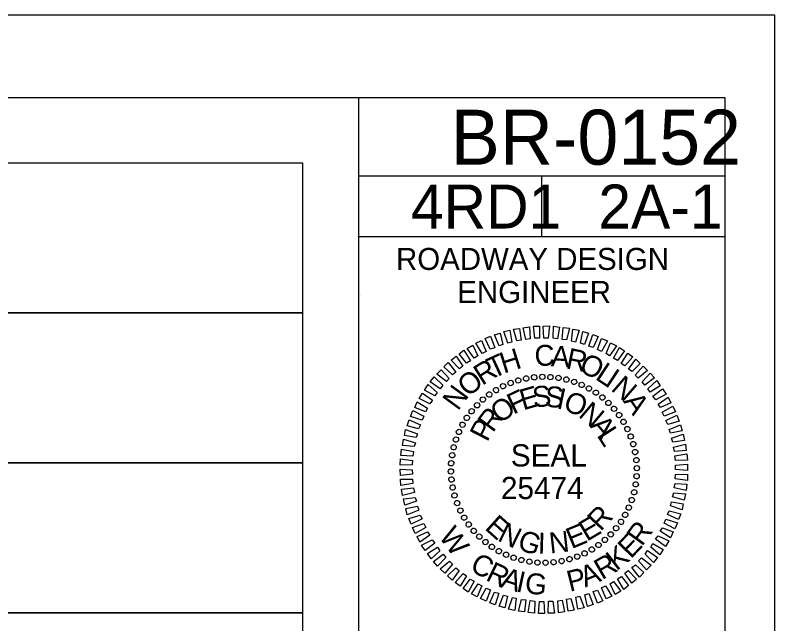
# Model space of a CAD drawing. Extents: x 1553884 to 1554215, y 810431 to 810779.
# Drawn here: x 1554125.27 to 1554156.35, y 810754.53 to 810779.43 of the extents above; entities that cross this region are included whole.
import ezdxf

# ---------------------------------------------------------------- set-up
doc = ezdxf.new("R2010")
doc.units = 0
for name, color, linetype in [('Exist Structure Minor Drop Inlet Top Elevation', 7, 'Continuous'), ('Old_Level_2', 7, 'Continuous'), ('Prop Dimension', 7, 'Continuous'), ('Prop Lane Arrow CELL', 7, 'Continuous'), ('Typical Arrow Superelevation CELL', 7, 'Continuous')]:
    doc.layers.add(name, color=color, linetype=linetype)

msp = doc.modelspace()

# ---------------------------------------------------------------- linework, layer by layer
at = {"layer": 'Exist Structure Minor Drop Inlet Top Elevation'}
for p, q in [((1554139.415, 810767.944), (1554139.415, 810767.944)), ((1554145.537, 810764.389), (1554145.537, 810764.389)), ((1554145.853, 810764.493), (1554145.853, 810764.493)), ((1554146.178, 810764.567), (1554146.178, 810764.567)), ((1554146.503, 810764.618), (1554146.503, 810764.618)), ((1554146.837, 810764.639), (1554146.837, 810764.639)), ((1554147.171, 810764.63), (1554147.171, 810764.63)), ((1554147.497, 810764.59), (1554147.497, 810764.59)), ((1554147.824, 810764.527), (1554147.824, 810764.527)), ((1554148.144, 810764.435), (1554148.144, 810764.435)), ((1554144.943, 810764.098), (1554144.943, 810764.098)), ((1554145.236, 810764.255), (1554145.236, 810764.255)), ((1554148.45, 810764.311), (1554148.45, 810764.311)), ((1554148.748, 810764.165), (1554148.748, 810764.165)), ((1554144.665, 810763.911), (1554144.665, 810763.911)), ((1554149.032, 810763.987), (1554149.032, 810763.987)), ((1554149.301, 810763.795), (1554149.301, 810763.795)), ((1554144.165, 810763.478), (1554144.165, 810763.478)), ((1554144.403, 810763.71), (1554144.403, 810763.71)), ((1554149.547, 810763.572), (1554149.547, 810763.572)), ((1554143.942, 810763.231), (1554143.942, 810763.231)), ((1554149.779, 810763.333), (1554149.779, 810763.333)), ((1554143.749, 810762.962), (1554143.749, 810762.962)), ((1554149.981, 810763.071), (1554149.981, 810763.071)), ((1554143.572, 810762.679), (1554143.572, 810762.679)), ((1554150.168, 810762.794), (1554150.168, 810762.794)), ((1554143.426, 810762.38), (1554143.426, 810762.38)), ((1554150.324, 810762.501), (1554150.324, 810762.501)), ((1554150.459, 810762.2), (1554150.459, 810762.2)), ((1554143.302, 810762.075), (1554143.302, 810762.075)), ((1554143.209, 810761.755), (1554143.209, 810761.755)), ((1554150.563, 810761.883), (1554150.563, 810761.883)), ((1554143.146, 810761.428), (1554143.146, 810761.428)), ((1554150.637, 810761.558), (1554150.637, 810761.558)), ((1554143.107, 810761.101), (1554143.107, 810761.101)), ((1554150.688, 810761.233), (1554150.688, 810761.233)), ((1554143.097, 810760.767), (1554143.097, 810760.767)), ((1554146.903, 810760.833), (1554146.903, 810760.833)), ((1554150.709, 810760.9), (1554150.709, 810760.9)), ((1554143.118, 810760.434), (1554143.118, 810760.434)), ((1554150.699, 810760.566), (1554150.699, 810760.566)), ((1554143.17, 810760.108), (1554143.17, 810760.108)), ((1554150.66, 810760.239), (1554150.66, 810760.239)), ((1554143.243, 810759.784), (1554143.243, 810759.784)), ((1554150.597, 810759.912), (1554150.597, 810759.912)), ((1554143.348, 810759.467), (1554143.348, 810759.467)), ((1554150.504, 810759.592), (1554150.504, 810759.592)), ((1554143.482, 810759.166), (1554143.482, 810759.166)), ((1554150.38, 810759.286), (1554150.38, 810759.286)), ((1554143.639, 810758.873), (1554143.639, 810758.873)), ((1554150.234, 810758.988), (1554150.234, 810758.988)), ((1554143.825, 810758.596), (1554143.825, 810758.596)), ((1554150.057, 810758.705), (1554150.057, 810758.705)), ((1554144.027, 810758.334), (1554144.027, 810758.334)), ((1554149.641, 810758.189), (1554149.641, 810758.189)), ((1554149.865, 810758.436), (1554149.865, 810758.436)), ((1554144.259, 810758.095), (1554144.259, 810758.095)), ((1554144.505, 810757.872), (1554144.505, 810757.872)), ((1554149.403, 810757.957), (1554149.403, 810757.957)), ((1554144.774, 810757.68), (1554144.774, 810757.68)), ((1554148.864, 810757.569), (1554148.864, 810757.569)), ((1554149.141, 810757.756), (1554149.141, 810757.756)), ((1554145.058, 810757.502), (1554145.058, 810757.502)), ((1554145.356, 810757.356), (1554145.356, 810757.356)), ((1554145.662, 810757.232), (1554145.662, 810757.232)), ((1554148.269, 810757.278), (1554148.269, 810757.278)), ((1554148.571, 810757.412), (1554148.571, 810757.412)), ((1554145.982, 810757.139), (1554145.982, 810757.139)), ((1554146.309, 810757.077), (1554146.309, 810757.077)), ((1554146.636, 810757.037), (1554146.636, 810757.037)), ((1554146.969, 810757.028), (1554146.969, 810757.028)), ((1554147.303, 810757.049), (1554147.303, 810757.049)), ((1554147.628, 810757.1), (1554147.628, 810757.1)), ((1554147.953, 810757.174), (1554147.953, 810757.174))]:
    msp.add_line(p, q, dxfattribs=at)
for points in [[(1554145.795, 810766.107), (1554145.658, 810766.583), (1554145.907, 810766.617), (1554145.976, 810766.133)], [(1554146.158, 810766.167), (1554146.058, 810766.643), (1554146.308, 810766.685), (1554146.339, 810766.193)], [(1554146.536, 810766.211), (1554146.475, 810766.703), (1554146.725, 810766.707), (1554146.718, 810766.214)], [(1554146.9, 810766.218), (1554146.876, 810766.71), (1554147.126, 810766.714), (1554147.082, 810766.221)], [(1554147.279, 810766.209), (1554147.293, 810766.702), (1554147.544, 810766.669), (1554147.462, 810766.189)], [(1554147.644, 810766.162), (1554147.696, 810766.649), (1554147.947, 810766.623), (1554147.827, 810766.143)], [(1554148.032, 810766.093), (1554148.092, 810766.587), (1554148.351, 810766.539), (1554148.192, 810766.058)], [(1554144.709, 810765.762), (1554144.496, 810766.198), (1554144.715, 810766.293), (1554144.89, 810765.819)], [(1554145.07, 810765.898), (1554144.881, 810766.349), (1554145.114, 810766.422), (1554145.229, 810765.953)], [(1554145.432, 810766.01), (1554145.257, 810766.485), (1554145.514, 810766.542), (1554145.591, 810766.051)], [(1554148.398, 810766.009), (1554148.496, 810766.481), (1554148.732, 810766.416), (1554148.558, 810765.958)], [(1554148.741, 810765.886), (1554148.899, 810766.366), (1554149.121, 810766.279), (1554148.924, 810765.836)], [(1554144.055, 810765.402), (1554143.76, 810765.799), (1554143.993, 810765.932), (1554144.198, 810765.496)], [(1554144.378, 810765.59), (1554144.121, 810766.01), (1554144.354, 810766.12), (1554144.544, 810765.668)], [(1554149.092, 810765.748), (1554149.266, 810766.206), (1554149.503, 810766.104), (1554149.26, 810765.675)], [(1554149.444, 810765.587), (1554149.633, 810766.03), (1554149.871, 810765.905), (1554149.59, 810765.499)], [(1554143.733, 810765.199), (1554143.438, 810765.573), (1554143.633, 810765.728), (1554143.898, 810765.293)], [(1554149.751, 810765.395), (1554150.001, 810765.839), (1554150.201, 810765.691), (1554149.919, 810765.307)], [(1554143.449, 810764.959), (1554143.109, 810765.317), (1554143.311, 810765.48), (1554143.591, 810765.068)], [(1554150.065, 810765.181), (1554150.331, 810765.603), (1554150.538, 810765.447), (1554150.211, 810765.077)], [(1554150.365, 810764.951), (1554150.661, 810765.358), (1554150.846, 810765.179), (1554150.511, 810764.847)], [(1554143.157, 810764.719), (1554142.81, 810765.039), (1554142.989, 810765.224), (1554143.299, 810764.828)], [(1554150.643, 810764.698), (1554150.962, 810765.068), (1554151.147, 810764.889), (1554150.766, 810764.579)], [(1554142.912, 810764.442), (1554142.52, 810764.738), (1554142.699, 810764.923), (1554143.031, 810764.565)], [(1554150.92, 810764.43), (1554151.255, 810764.784), (1554151.425, 810764.59), (1554151.029, 810764.288)], [(1554142.659, 810764.142), (1554142.252, 810764.43), (1554142.416, 810764.63), (1554142.763, 810764.287)], [(1554151.16, 810764.146), (1554151.518, 810764.478), (1554151.666, 810764.261), (1554151.254, 810764.003)], [(1554142.444, 810763.85), (1554142.023, 810764.093), (1554142.163, 810764.315), (1554142.533, 810763.995)], [(1554151.363, 810763.839), (1554151.759, 810764.141), (1554151.907, 810763.924), (1554151.479, 810763.697)], [(1554142.23, 810763.535), (1554141.794, 810763.747), (1554141.934, 810763.97), (1554142.341, 810763.681)], [(1554151.573, 810763.516), (1554151.985, 810763.796), (1554152.095, 810763.563), (1554151.667, 810763.374)], [(1554142.054, 810763.206), (1554141.618, 810763.38), (1554141.72, 810763.617), (1554142.142, 810763.351)], [(1554141.916, 810762.855), (1554141.443, 810763.013), (1554141.545, 810763.25), (1554141.989, 810763.023)], [(1554151.738, 810763.193), (1554152.174, 810763.436), (1554152.284, 810763.202), (1554151.817, 810763.027)], [(1554141.778, 810762.511), (1554141.305, 810762.632), (1554141.392, 810762.868), (1554141.851, 810762.671)], [(1554151.888, 810762.847), (1554152.339, 810763.059), (1554152.435, 810762.826), (1554151.967, 810762.689)], [(1554152.023, 810762.485), (1554152.498, 810762.675), (1554152.555, 810762.426), (1554152.079, 810762.327)], [(1554141.678, 810762.145), (1554141.199, 810762.228), (1554141.247, 810762.479), (1554141.728, 810762.305)], [(1554152.121, 810762.123), (1554152.596, 810762.283), (1554152.653, 810762.026), (1554152.176, 810761.964)], [(1554141.593, 810761.78), (1554141.115, 810761.824), (1554141.163, 810762.083), (1554141.644, 810761.94)], [(1554141.539, 810761.392), (1554141.054, 810761.421), (1554141.079, 810761.68), (1554141.574, 810761.575)], [(1554152.203, 810761.76), (1554152.694, 810761.882), (1554152.728, 810761.625), (1554152.244, 810761.579)], [(1554141.515, 810761.027), (1554141.023, 810761.019), (1554141.033, 810761.277), (1554141.527, 810761.21)], [(1554152.262, 810761.397), (1554152.754, 810761.482), (1554152.773, 810761.224), (1554152.281, 810761.216)], [(1554152.284, 810761.018), (1554152.776, 810761.065), (1554152.781, 810760.807), (1554152.287, 810760.836)], [(1554141.522, 810760.648), (1554141.03, 810760.602), (1554141.025, 810760.86), (1554141.519, 810760.831)], [(1554152.291, 810760.639), (1554152.783, 810760.648), (1554152.773, 810760.39), (1554152.279, 810760.457)], [(1554141.544, 810760.27), (1554141.052, 810760.185), (1554141.033, 810760.443), (1554141.525, 810760.451)], [(1554141.603, 810759.907), (1554141.112, 810759.784), (1554141.078, 810760.042), (1554141.562, 810760.088)], [(1554152.267, 810760.275), (1554152.753, 810760.245), (1554152.727, 810759.987), (1554152.232, 810760.092)], [(1554152.213, 810759.887), (1554152.691, 810759.842), (1554152.643, 810759.584), (1554152.163, 810759.727)], [(1554141.685, 810759.544), (1554141.21, 810759.384), (1554141.153, 810759.641), (1554141.63, 810759.702)], [(1554152.128, 810759.522), (1554152.607, 810759.439), (1554152.559, 810759.188), (1554152.078, 810759.362)], [(1554141.783, 810759.182), (1554141.308, 810758.992), (1554141.251, 810759.241), (1554141.727, 810759.34)], [(1554152.028, 810759.156), (1554152.501, 810759.035), (1554152.414, 810758.799), (1554151.955, 810758.995)], [(1554141.918, 810758.82), (1554141.467, 810758.608), (1554141.372, 810758.841), (1554141.839, 810758.978)], [(1554151.89, 810758.812), (1554152.363, 810758.654), (1554152.261, 810758.417), (1554151.817, 810758.644)], [(1554142.068, 810758.474), (1554141.632, 810758.231), (1554141.522, 810758.465), (1554141.989, 810758.639)], [(1554142.233, 810758.151), (1554141.821, 810757.871), (1554141.711, 810758.104), (1554142.139, 810758.293)], [(1554151.752, 810758.461), (1554152.188, 810758.287), (1554152.086, 810758.05), (1554151.664, 810758.316)], [(1554142.443, 810757.828), (1554142.047, 810757.526), (1554141.899, 810757.743), (1554142.327, 810757.97)], [(1554151.576, 810758.132), (1554152.012, 810757.92), (1554151.872, 810757.697), (1554151.465, 810757.986)], [(1554142.646, 810757.521), (1554142.288, 810757.189), (1554142.14, 810757.406), (1554142.552, 810757.664)], [(1554151.362, 810757.817), (1554151.783, 810757.574), (1554151.643, 810757.352), (1554151.273, 810757.672)], [(1554142.886, 810757.237), (1554142.551, 810756.882), (1554142.38, 810757.076), (1554142.777, 810757.379)], [(1554150.894, 810757.225), (1554151.286, 810756.929), (1554151.107, 810756.744), (1554150.775, 810757.102)], [(1554151.147, 810757.525), (1554151.554, 810757.237), (1554151.39, 810757.037), (1554151.043, 810757.379)], [(1554143.164, 810756.969), (1554142.844, 810756.599), (1554142.659, 810756.778), (1554143.04, 810757.088)], [(1554150.649, 810756.948), (1554150.996, 810756.628), (1554150.817, 810756.443), (1554150.507, 810756.839)], [(1554143.441, 810756.716), (1554143.145, 810756.309), (1554142.96, 810756.488), (1554143.295, 810756.819)], [(1554150.357, 810756.708), (1554150.697, 810756.35), (1554150.495, 810756.187), (1554150.215, 810756.599)], [(1554143.741, 810756.486), (1554143.475, 810756.064), (1554143.268, 810756.22), (1554143.595, 810756.59)], [(1554144.056, 810756.272), (1554143.805, 810755.827), (1554143.606, 810755.976), (1554143.887, 810756.36)], [(1554150.073, 810756.468), (1554150.368, 810756.094), (1554150.173, 810755.939), (1554149.908, 810756.374)], [(1554144.362, 810756.08), (1554144.173, 810755.637), (1554143.935, 810755.761), (1554144.217, 810756.168)], [(1554144.714, 810755.919), (1554144.54, 810755.461), (1554144.303, 810755.563), (1554144.546, 810755.992)], [(1554149.428, 810756.077), (1554149.685, 810755.657), (1554149.452, 810755.547), (1554149.262, 810755.999)], [(1554149.751, 810756.265), (1554150.046, 810755.868), (1554149.813, 810755.735), (1554149.608, 810756.171)], [(1554145.065, 810755.781), (1554144.907, 810755.301), (1554144.685, 810755.388), (1554144.882, 810755.831)], [(1554145.408, 810755.658), (1554145.311, 810755.186), (1554145.074, 810755.25), (1554145.248, 810755.708)], [(1554148.736, 810755.769), (1554148.925, 810755.318), (1554148.692, 810755.245), (1554148.577, 810755.713)], [(1554149.097, 810755.905), (1554149.31, 810755.469), (1554149.091, 810755.374), (1554148.916, 810755.848)], [(1554145.774, 810755.574), (1554145.714, 810755.08), (1554145.456, 810755.128), (1554145.614, 810755.609)], [(1554146.162, 810755.505), (1554146.11, 810755.018), (1554145.859, 810755.044), (1554145.98, 810755.524)], [(1554146.527, 810755.458), (1554146.513, 810754.965), (1554146.262, 810754.998), (1554146.344, 810755.477)], [(1554146.906, 810755.449), (1554146.93, 810754.957), (1554146.68, 810754.952), (1554146.724, 810755.446)], [(1554147.27, 810755.456), (1554147.331, 810754.964), (1554147.081, 810754.959), (1554147.088, 810755.452)], [(1554147.648, 810755.5), (1554147.748, 810755.024), (1554147.498, 810754.982), (1554147.467, 810755.474)], [(1554148.011, 810755.559), (1554148.148, 810755.084), (1554147.899, 810755.05), (1554147.83, 810755.534)], [(1554148.374, 810755.657), (1554148.549, 810755.182), (1554148.292, 810755.125), (1554148.215, 810755.616)]]:
    msp.add_lwpolyline(points, close=True, dxfattribs=at)
for centre, major_axis in [((1554146.177, 810764.564), (-0.021, 0.107)), ((1554146.505, 810764.613), (-0.011, 0.109)), ((1554146.836, 810764.633), (-0.002, 0.109)), ((1554147.168, 810764.624), (0.008, 0.109)), ((1554147.497, 810764.587), (0.017, 0.108)), ((1554145.235, 810764.249), (-0.0479, 0.0981)), ((1554145.54, 810764.381), (-0.039, 0.102)), ((1554145.854, 810764.486), (-0.03, 0.105)), ((1554147.823, 810764.521), (0.026, 0.106)), ((1554148.141, 810764.427), (0.036, 0.103)), ((1554148.449, 810764.305), (0.0444, 0.0997)), ((1554144.944, 810764.091), (-0.0562, 0.0936)), ((1554148.746, 810764.157), (0.0529, 0.0955)), ((1554149.029, 810763.984), (0.0611, 0.0905)), ((1554144.407, 810763.701), (-0.0716, 0.0824)), ((1554144.667, 810763.907), (-0.0642, 0.0883)), ((1554149.296, 810763.786), (0.0687, 0.0849)), ((1554144.167, 810763.472), (-0.0785, 0.0758)), ((1554149.544, 810763.566), (0.0758, 0.0785)), ((1554149.773, 810763.326), (0.0824, 0.0716)), ((1554143.947, 810763.224), (-0.0849, 0.0687)), ((1554149.979, 810763.066), (0.0883, 0.0642)), ((1554143.749, 810762.957), (-0.0905, 0.0611)), ((1554150.163, 810762.789), (0.0936, 0.0562)), ((1554143.576, 810762.674), (-0.0955, 0.0529)), ((1554150.321, 810762.498), (0.0981, 0.0479)), ((1554143.428, 810762.377), (-0.0997, 0.0444)), ((1554150.453, 810762.193), (0.102, 0.039)), ((1554143.306, 810762.069), (-0.103, 0.036)), ((1554150.558, 810761.879), (0.105, 0.03)), ((1554143.212, 810761.751), (-0.106, 0.026)), ((1554150.636, 810761.556), (0.107, 0.021)), ((1554143.146, 810761.425), (-0.108, 0.017)), ((1554150.685, 810761.228), (0.109, 0.011)), ((1554143.108, 810761.096), (-0.109, 0.008)), ((1554150.705, 810760.897), (0.109, 0.002)), ((1554143.1, 810760.764), (-0.109, -0.002)), ((1554150.697, 810760.565), (0.109, -0.008)), ((1554143.12, 810760.433), (-0.109, -0.011)), ((1554150.659, 810760.236), (0.108, -0.017)), ((1554143.169, 810760.105), (-0.107, -0.021)), ((1554150.593, 810759.91), (0.106, -0.026)), ((1554143.247, 810759.782), (-0.105, -0.03)), ((1554150.499, 810759.592), (0.103, -0.036)), ((1554143.352, 810759.467), (-0.102, -0.039)), ((1554150.377, 810759.284), (0.0997, -0.0444)), ((1554143.484, 810759.163), (-0.0981, -0.0479)), ((1554150.229, 810758.987), (0.0955, -0.0529)), ((1554143.642, 810758.872), (-0.0936, -0.0562)), ((1554150.056, 810758.704), (0.0905, -0.0611)), ((1554143.826, 810758.595), (-0.0883, -0.0642)), ((1554149.858, 810758.437), (0.0849, -0.0687)), ((1554144.032, 810758.335), (-0.0824, -0.0716)), ((1554144.261, 810758.095), (-0.0758, -0.0785)), ((1554149.638, 810758.188), (0.0785, -0.0758)), ((1554144.509, 810757.875), (-0.0687, -0.0849)), ((1554149.138, 810757.754), (0.0642, -0.0883)), ((1554149.398, 810757.96), (0.0716, -0.0824)), ((1554144.776, 810757.677), (-0.0611, -0.0905)), ((1554145.059, 810757.504), (-0.0529, -0.0955)), ((1554148.57, 810757.412), (0.0479, -0.0981)), ((1554148.861, 810757.57), (0.0562, -0.0936)), ((1554145.356, 810757.356), (-0.0444, -0.0997)), ((1554145.664, 810757.234), (-0.036, -0.103)), ((1554145.982, 810757.14), (-0.026, -0.106)), ((1554147.951, 810757.175), (0.03, -0.105)), ((1554148.265, 810757.28), (0.039, -0.102)), ((1554146.308, 810757.074), (-0.017, -0.108)), ((1554146.637, 810757.036), (-0.008, -0.109)), ((1554146.969, 810757.028), (0.002, -0.109)), ((1554147.3, 810757.048), (0.011, -0.109)), ((1554147.628, 810757.097), (0.021, -0.107))]:
    msp.add_ellipse(centre, major_axis=major_axis, ratio=0.999708, dxfattribs=at)
at = {"layer": 'Old_Level_2'}
for p, q in [((1554154.325, 810776.052), (1553906.825, 810776.052)), ((1554139.321, 810617.805), (1554139.325, 810776.052)), ((1554154.321, 810617.805), (1554154.325, 810776.052)), ((1554154.325, 810772.839), (1554139.325, 810772.839)), ((1554146.825, 810770.364), (1554146.825, 810772.839)), ((1554154.325, 810770.364), (1554139.325, 810770.364))]:
    msp.add_line(p, q, dxfattribs=at)
msp.add_circle((1554139.325, 810770.364), 0.009, dxfattribs=at)
at = {"layer": 'Prop Dimension'}
msp.add_lwpolyline([(1554077.027, 810773.388), (1554137.029, 810773.388), (1554137.029, 810767.252), (1554077.027, 810767.252)], close=True, dxfattribs=at)
for points in [[(1554083.164, 810761.114), (1554077.027, 810761.114), (1554077.027, 810767.252), (1554137.027, 810767.252), (1554137.027, 810761.114), (1554083.164, 810761.114), (1554083.164, 810767.252)], [(1554083.164, 810754.977), (1554077.027, 810754.977), (1554077.027, 810761.114), (1554137.027, 810761.114), (1554137.027, 810754.977), (1554083.164, 810754.977), (1554083.164, 810761.114)], [(1554083.164, 810748.839), (1554077.027, 810748.839), (1554077.027, 810754.977), (1554137.027, 810754.977), (1554137.027, 810748.839), (1554083.164, 810748.839), (1554083.164, 810754.977)]]:
    msp.add_lwpolyline(points, dxfattribs=at)
at = {"layer": 'Prop Lane Arrow CELL'}
for p, q in [((1554156.35, 810779.427), (1553901.353, 810779.427)), ((1554156.35, 810614.43), (1554156.35, 810779.427))]:
    msp.add_line(p, q, dxfattribs=at)

# ---------------------------------------------------------------- texts
at = {"layer": 'Exist Structure Minor Drop Inlet Top Elevation'}
for s, height, rotation, p in [('C', 0.855, 2.9171, (1554146.539, 810765.064)), ('H', 0.855, 17.4535, (1554145.257, 810764.764)), ('A', 0.855, 355.649, (1554147.177, 810765.069)), ('R', 0.855, 348.3808, (1554147.77, 810764.988)), ('T', 0.855, 24.7216, (1554144.817, 810764.545)), ('O', 0.855, 333.8445, (1554148.29, 810764.88)), ('R', 0.855, 31.9898, (1554144.375, 810764.258)), ('L', 0.855, 326.5763, (1554148.962, 810764.559)), ('O', 0.855, 39.2579, (1554143.802, 810763.78)), ('I', 0.855, 326.5763, (1554149.348, 810764.304)), ('N', 0.855, 319.3082, (1554149.609, 810764.104)), ('N', 0.855, 53.7943, (1554143.385, 810763.212)), ('F', 0.855, 25.3292, (1554145.653, 810763.08)), ('E', 0.855, 15.9853, (1554146.053, 810763.258)), ('S', 0.855, 6.6414, (1554146.482, 810763.367)), ('S', 0.855, 357.2975, (1554146.935, 810763.4)), ('I', 0.855, 347.9535, (1554147.387, 810763.353)), ('O', 0.855, 338.6096, (1554147.647, 810763.297)), ('A', 0.855, 304.7718, (1554150.128, 810763.63)), ('O', 0.855, 34.6731, (1554145.089, 810762.697)), ('N', 0.855, 319.9218, (1554148.277, 810763.029)), ('R', 0.855, 53.361, (1554144.811, 810762.319)), ('P', 0.855, 62.7049, (1554144.587, 810761.938)), ('A', 0.855, 310.5779, (1554148.757, 810762.611)), ('L', 0.855, 302.7465, (1554149.046, 810762.244)), ('SEAL', 0.9096, 0, (1554145.549, 810760.965)), ('25474', 0.9099, 0, (1554145.144, 810759.631)), ('R', 0.855, 46.7271, (1554149.224, 810758.285)), ('E', 0.855, 317.8985, (1554144.446, 810758.422)), ('E', 0.855, 30.5764, (1554148.659, 810757.879)), ('W', 0.855, 305.9992, (1554142.575, 810758.105)), ('N', 0.855, 334.0491, (1554144.967, 810757.954)), ('E', 0.855, 22.5011, (1554148.031, 810757.581)), ('R', 0.855, 54, (1554150.913, 810757.667)), ('G', 0.855, 342.1244, (1554145.776, 810757.586)), ('I', 0.855, 358.2751, (1554146.644, 810757.403)), ('N', 0.855, 6.3504, (1554147.162, 810757.404)), ('E', 0.855, 46, (1554150.456, 810757.163)), ('.', 0.855, 310.4999, (1554142.971, 810757.576)), ('K', 0.855, 38, (1554149.869, 810756.672)), ('C', 0.855, 334, (1554143.836, 810756.705)), ('R', 0.855, 30, (1554149.278, 810756.31)), ('R', 0.855, 334, (1554144.481, 810756.334)), ('A', 0.855, 22, (1554148.591, 810756.009)), ('A', 0.855, 342, (1554145.095, 810756.053)), ('I', 0.855, 347.5, (1554145.728, 810755.864)), ('G', 0.855, 354, (1554146.098, 810755.784)), ('P', 0.855, 14, (1554147.962, 810755.836))]:
    msp.add_text(s, height=height, rotation=rotation, dxfattribs=at).set_placement(p)
at = {"layer": 'Typical Arrow Superelevation CELL'}
for s, height, p in [('BR-0152', 2.25, (1554143.092, 810773.311)), ('4RD1', 1.8, (1554141.461, 810770.701)), ('2A-1', 1.8, (1554149.129, 810770.701)), ('ROADWAY DESIGN', 0.9, (1554140.853, 810769.006)), ('ENGINEER', 0.9, (1554143.36, 810767.656))]:
    msp.add_text(s, height=height, dxfattribs=at).set_placement(p)

doc.saveas('drawing.dxf')
